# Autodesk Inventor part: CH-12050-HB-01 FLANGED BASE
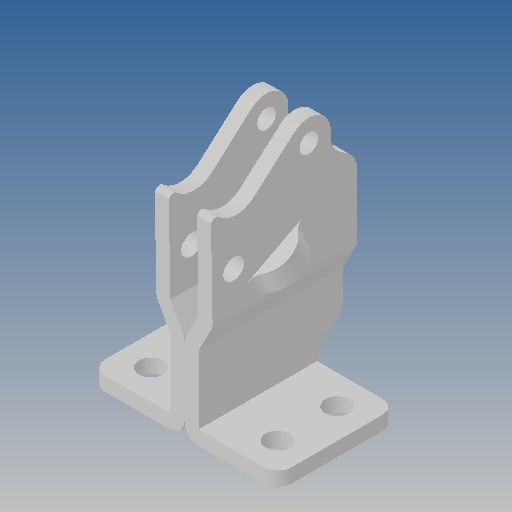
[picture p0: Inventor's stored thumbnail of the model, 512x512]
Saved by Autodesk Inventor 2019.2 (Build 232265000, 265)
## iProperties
Created: 2012-07
Part Number: CH-12050-HB-01 FLANGED BASE
Material: Ogólny
Document SubType Name: Modeling
Designer: CADENGINEERING4
Density: 1 g/cm^3
Appearance: Domyślna
Author: CADENGINEERING4
Revision Number: ÈÎºÎ
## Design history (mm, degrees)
feature "¾µÏò1"
feature "Ô²½Ç3"
node "Bryła1"
node "Bryła2"
